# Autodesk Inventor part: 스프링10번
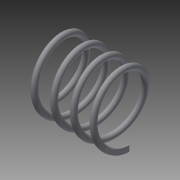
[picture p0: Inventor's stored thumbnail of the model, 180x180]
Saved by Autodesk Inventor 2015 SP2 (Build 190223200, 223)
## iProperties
Created: 2015-06
Part Number: 스프링10번
Material: 일반
Document SubType Name: Modeling
Designer: AMC
Density: 1 g/cm^3
Appearance: 기본값
Author: AMC
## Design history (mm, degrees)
sketch "스케치1"
  geometry: L1 (0, 0)-(0, -8); L2 (0, 0)-(20.5, 0); C1 r 0.75 at (0, -8)
  constraints: 4 end point, 1 centre point, 1 coincident, 1 horizontal, 1 vertical
  dimensions: "d0" = 8 distance of L1.start L1.end; "d1" = 1.5 diameter of C1; "d2" = 20.5 distance of L1.start L2.end (derived)
feature "코일1" sketch "스케치1" pitch "d3" = 10; turns "d5" = 4; dims "d4" = 20.5 (= d2), "d6" = 0, angle "d7" = 90 deg, angle "d8" = 90 deg, "d9" = 0, "d10" = 0
sketch "스케치2"
  geometry: L1 (0, -21.66)-(6.113, -21.66); L2 (6.113, -21.66)-(6.113, 4.55); L3 (6.113, 4.55)-(0, 4.55); L4 (0, 4.55)-(0, -21.66); L5 (-20.5, 3.586)-(-30.148, 3.586); L6 (-30.148, 3.586)-(-30.148, -23.831); L7 (-30.148, -23.831)-(-20.5, -23.831); L8 (-20.5, -23.831)-(-20.5, 3.586); 1 further point
  constraints: 16 end point, 4 parallel, 2 horizontal, 2 perpendicular, 1 point on line
  dimensions: "d11" = 20.5 distance between parallel lines of L4 L8 (= d2)
extrude "돌출1" cut sketch "스케치2" stored distance "d12" = 50; taper "d13" = 0 deg
node "솔리드1"
